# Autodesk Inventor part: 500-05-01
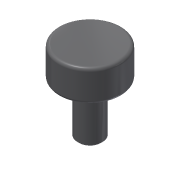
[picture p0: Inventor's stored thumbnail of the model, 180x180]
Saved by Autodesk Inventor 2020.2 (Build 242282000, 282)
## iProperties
Created: 2015-10
Part Number: 500-05-01
Material: Stal
Document SubType Name: Modeling
Designer: F.Stasiak
Density: 7.85 g/cm^3
Appearance: Płyta
Description: Rolka
Manager: www.cadconsulting.pl
Company: Fabian Stasiak CAD Consulting
Author: F.Stasiak
Subject: Zbiór ćwiczeń. Autodesk Inventor 2020. Kurs podstawowy
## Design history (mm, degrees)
sketch "Szkic1"
  geometry: C1 r 20 at (0, 0); 1 further point
  constraints: 1 centre point, 1 coincident
  dimensions: "d0" = 40 diameter of C1
extrude "Wyciągnięcie proste1" new body sketch "Szkic1" distance "d1" = 80; taper "d2" = 0 deg
sketch "Szkic2"
  geometry: C1 r 20 at (0, 0) reference; C2 r 50 at (0, 0)
  constraints: 1 centre point, 1 coincident
  dimensions: "d3" = 100 diameter of C2
extrude "Wyciągnięcie proste2" join sketch "Szkic2" distance "d4" = 50; taper "d5" = 0 deg
sketch "Szkic3"
  geometry: C1 r 20 at (0, 0) reference; C2 r 20 at (0, 0) reference; C3 r 30 at (0, 0)
  constraints: 1 centre point, 1 coincident
  dimensions: "d6" = 60 diameter of C3
extrude "Wyciągnięcie proste3" join sketch "Szkic3" distance "d7" = 5; taper "d8" = 0 deg
fillet "Zaokrąglenie1" dims "d9" = 5
chamfer "Faza1" distance "d10" = 3; stored, may be unused: second distance "d11" = 2, angle "d12" = 45 deg
node "Bryła1"
